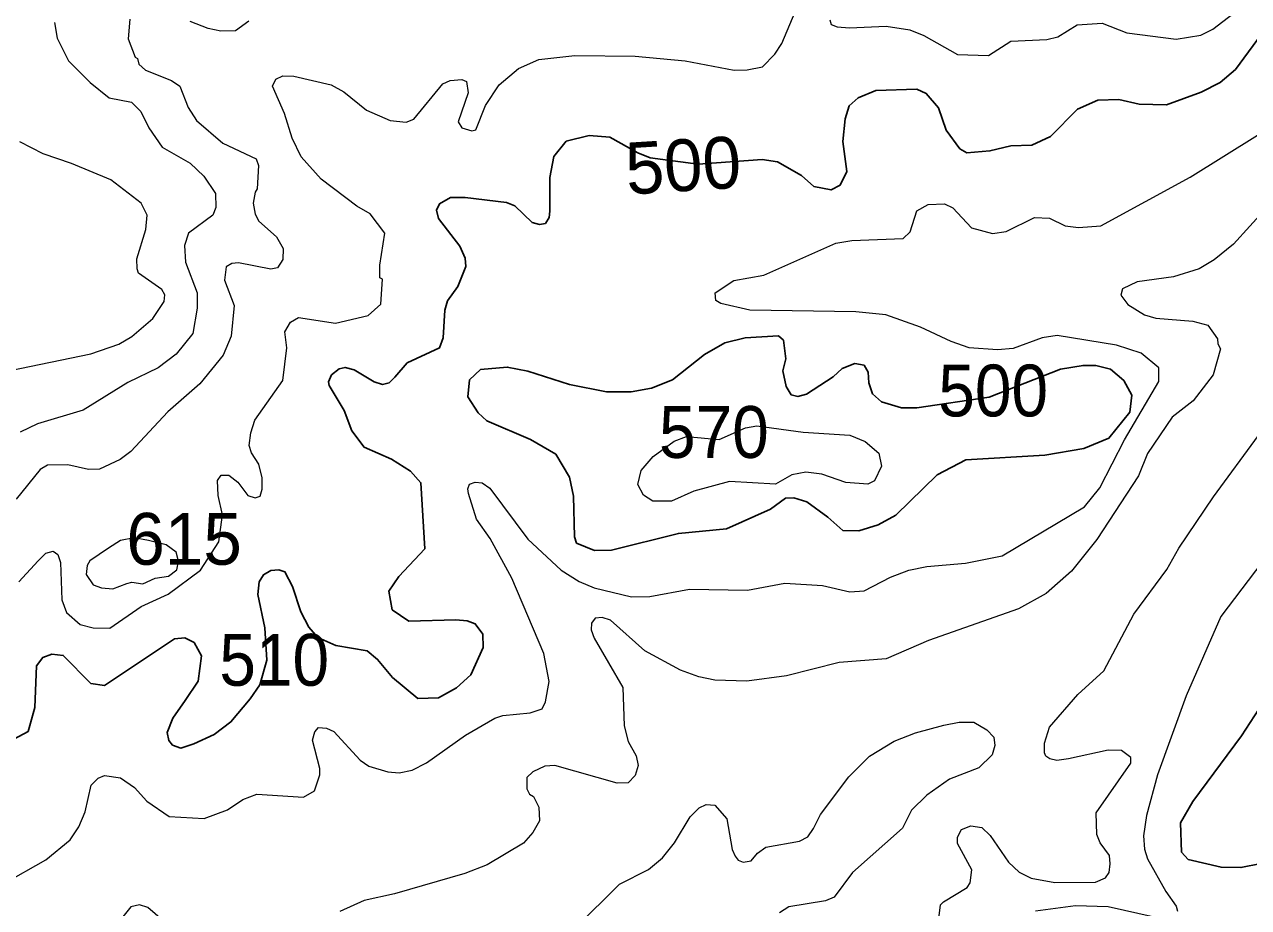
# Model space of a CAD drawing. Extents: x 499.9 to 555.3, y 9281.5 to 9336.8.
# Drawn here: x 542.724 to 546.505, y 9285.393 to 9288.118 of the extents above; entities that cross this region are included whole.
import ezdxf
from ezdxf.enums import TextEntityAlignment as Align

# ---------------------------------------------------------------- set-up
doc = ezdxf.new("R2010")
doc.units = 0
doc.header["$LTSCALE"] = 0.064
doc.layers.add('1', color=7, linetype='Continuous', lineweight=25)
doc.layers.add('2', color=7, linetype='Continuous', lineweight=13)
doc.layers.add('21', color=7, linetype='Continuous')
doc.layers.add('61', color=7, linetype='Continuous')

msp = doc.modelspace()

# ---------------------------------------------------------------- linework, layer by layer
at = {"layer": '1'}
for points in [[(545.354, 9287.915), (545.4801, 9287.9184), (545.5095, 9287.9048), (545.5474, 9287.8606), (545.5707, 9287.7925), (545.613, 9287.7349), (545.6348, 9287.7217), (545.7058, 9287.7279), (545.7703, 9287.7437), (545.835, 9287.7462), (545.8935, 9287.7726), (545.9765, 9287.8566), (546.0393, 9287.8849), (546.1037, 9287.8868), (546.1674, 9287.8727), (546.2509, 9287.8708), (546.3583, 9287.9093), (546.4172, 9287.9396), (546.4645, 9287.9794), (546.5447, 9288.0889)], [(545.2642, 9287.6646), (545.2517, 9287.7571), (545.2585, 9287.8276), (545.2715, 9287.8672), (545.2991, 9287.8917), (545.354, 9287.915)], [(543.2715, 9286.1697), (543.261, 9286.0915), (543.2204, 9286.0314), (543.1828, 9285.9773), (543.1652, 9285.9331), (543.1703, 9285.9078), (543.1816, 9285.8939), (543.2068, 9285.8841), (543.2475, 9285.8976), (543.3103, 9285.9267), (543.3617, 9285.9653), (543.4214, 9286.037), (543.4509, 9286.0799), (543.4728, 9286.1565), (543.4668, 9286.2561), (543.4447, 9286.3589), (543.4489, 9286.3975), (543.463, 9286.4196), (543.4847, 9286.4328), (543.5095, 9286.4346), (543.5285, 9286.4293), (543.5522, 9286.3837), (543.5783, 9286.3049), (543.602, 9286.2575), (543.6304, 9286.2258), (543.6858, 9286.2015), (543.7831, 9286.1854), (543.815, 9286.1584), (543.8613, 9286.1029), (543.9393, 9286.0379), (544.0028, 9286.0394), (544.0584, 9286.0711), (544.1029, 9286.111), (544.1412, 9286.1952), (544.1397, 9286.2363), (544.1163, 9286.2678), (544.092, 9286.278), (544.0561, 9286.2808), (543.9112, 9286.2764), (543.8599, 9286.3116), (543.8496, 9286.3687), (543.8804, 9286.4147), (543.9612, 9286.5), (543.9486, 9286.7037), (543.9168, 9286.7394), (543.8583, 9286.7764), (543.7732, 9286.8135), (543.7356, 9286.8637), (543.7118, 9286.9265), (543.6651, 9287.0044), (543.6628, 9287.0156), (543.6727, 9287.0368), (543.696, 9287.0559), (543.7147, 9287.0596), (543.7425, 9287.0525), (543.8048, 9287.0153), (543.83, 9287.0075), (543.851, 9287.0125), (543.868, 9287.0298), (543.9065, 9287.0739), (544.0056, 9287.1202), (544.0173, 9287.1515), (544.0225, 9287.2362), (544.0307, 9287.2654), (544.0631, 9287.3093), (544.0871, 9287.3713), (544.0852, 9287.3975), (544.0691, 9287.4341), (544.0025, 9287.5193), (543.9972, 9287.5452), (544.0058, 9287.5651), (544.0403, 9287.5844), (544.0849, 9287.5845), (544.2128, 9287.5685), (544.239, 9287.5585), (544.2927, 9287.5068), (544.3147, 9287.5005), (544.333, 9287.5036), (544.3445, 9287.5221), (544.3471, 9287.5418), (544.3467, 9287.6458), (544.3597, 9287.7109), (544.3977, 9287.7577), (544.4684, 9287.7754), (544.532, 9287.7703), (544.619, 9287.7222), (544.6566, 9287.7067), (544.8049, 9287.6868), (545.0024, 9287.7015), (545.0495, 9287.6944), (545.1237, 9287.652), (545.1623, 9287.6181), (545.2157, 9287.6076), (545.2432, 9287.6227), (545.2642, 9287.6646)], [(542.9296, 9286.0845), (542.9714, 9286.0778), (543.188, 9286.222), (543.2197, 9286.2251), (543.2481, 9286.2108), (543.2715, 9286.1697)], [(542.6178, 9285.873), (542.7356, 9285.936), (542.7565, 9286.0105), (542.7616, 9286.1385), (542.7808, 9286.1645), (542.8089, 9286.1745), (542.844, 9286.1707), (542.9296, 9286.0845)], [(546.5369, 9286.0051), (546.4835, 9285.9223), (546.3324, 9285.7202), (546.295, 9285.654), (546.2982, 9285.5635), (546.3187, 9285.5412), (546.4198, 9285.517), (546.4813, 9285.516), (546.5437, 9285.5285)]]:
    msp.add_lwpolyline(points, dxfattribs=at)
msp.add_lwpolyline([(546.0786, 9287.0542), (546.0335, 9287.0652), (545.9935, 9287.0659), (545.9243, 9287.0539), (545.7036, 9286.9677), (545.4803, 9286.9354), (545.4326, 9286.9354), (545.3708, 9286.954), (545.3433, 9286.9783), (545.3316, 9287.012), (545.3297, 9287.045), (545.3172, 9287.0663), (545.2886, 9287.072), (545.2497, 9287.0565), (545.2215, 9287.0302), (545.14, 9286.9772), (545.113, 9286.9705), (545.0917, 9286.9754), (545.0768, 9287.0008), (545.0663, 9287.049), (545.0753, 9287.0865), (545.0689, 9287.1436), (545.0531, 9287.1577), (544.9506, 9287.1514), (544.8878, 9287.1356), (544.8249, 9287.0995), (544.7261, 9287.0217), (544.6609, 9286.9956), (544.5981, 9286.9846), (544.5219, 9286.9845), (544.4079, 9287.0066), (544.2789, 9287.0484), (544.2153, 9287.0609), (544.1328, 9287.0538), (544.0991, 9287.0216), (544.0939, 9286.9687), (544.1254, 9286.9194), (544.1519, 9286.8944), (544.2869, 9286.8377), (544.3656, 9286.7918), (544.4074, 9286.7215), (544.4198, 9286.6623), (544.4231, 9286.5366), (544.4293, 9286.5174), (544.4843, 9286.4947), (544.5376, 9286.4961), (544.7442, 9286.5473), (544.8925, 9286.5613), (545.0285, 9286.6224), (545.0746, 9286.6558), (545.1008, 9286.657), (545.1406, 9286.6451), (545.2055, 9286.5971), (545.2516, 9286.5566), (545.3015, 9286.555), (545.3612, 9286.5737), (545.4151, 9286.6032), (545.5433, 9286.7277), (545.6319, 9286.774), (545.8753, 9286.789), (545.9962, 9286.8098), (546.0735, 9286.8412), (546.138, 9286.9214), (546.1443, 9286.9746), (546.1194, 9287.0197)], close=True, dxfattribs=at)
at = {"layer": '2'}
for points in [[(543.7107, 9287.9104), (543.7801, 9287.8537), (543.854, 9287.8217), (543.9028, 9287.8169), (543.9268, 9287.8258), (544.0162, 9287.935), (544.0386, 9287.9459), (544.0749, 9287.9484), (544.0892, 9287.9428), (544.0951, 9287.9076), (544.0639, 9287.818), (544.0753, 9287.7994), (544.1059, 9287.7902), (544.1188, 9287.7934), (544.1485, 9287.8679), (544.1902, 9287.9325), (544.2505, 9287.9821), (544.3133, 9288.0099), (544.4245, 9288.0222), (544.6108, 9288.0207), (544.7653, 9288.0061), (544.9165, 9287.9778), (544.9563, 9287.978), (545.0037, 9287.9881), (545.0418, 9288.0264), (545.0631, 9288.0595), (545.113, 9288.1766)], [(545.2112, 9288.1322), (545.2156, 9288.1179), (545.2341, 9288.111), (545.2722, 9288.1083), (545.3861, 9288.1129), (545.459, 9288.1022), (545.5017, 9288.0844), (545.6064, 9288.0258), (545.7016, 9288.0227), (545.7702, 9288.0668), (545.8823, 9288.0716), (545.9162, 9288.0803), (545.9757, 9288.1173), (546.0527, 9288.1223), (546.1284, 9288.0926), (546.2812, 9288.0733), (546.3576, 9288.0858), (546.3949, 9288.1035), (546.4735, 9288.1644)], [(543.0496, 9288.1345), (543.0448, 9288.0738), (543.0663, 9288.0177), (543.0733, 9288.0134), (543.0772, 9287.9963), (543.098, 9287.9775), (543.1784, 9287.9457), (543.2036, 9287.9282), (543.2298, 9287.8625), (543.256, 9287.8224), (543.3369, 9287.7523), (543.4395, 9287.7032), (543.4471, 9287.6826), (543.4425, 9287.611), (543.4363, 9287.6005), (543.4308, 9287.5668), (543.4364, 9287.5327), (543.4485, 9287.5109), (543.5026, 9287.4625), (543.5237, 9287.4271), (543.5218, 9287.3925), (543.5053, 9287.3668), (543.4849, 9287.3629), (543.3852, 9287.3824), (543.3647, 9287.3806), (543.3475, 9287.3698), (543.3421, 9287.3291), (543.3723, 9287.2509), (543.363, 9287.1564), (543.3382, 9287.0973), (543.2654, 9287.0095), (543.1673, 9286.9225), (543.0532, 9286.8005), (543.0202, 9286.7757), (542.9563, 9286.7461), (542.9221, 9286.7445), (542.8585, 9286.7586), (542.7951, 9286.7577), (542.7731, 9286.7447), (542.6988, 9286.653)], [(542.8166, 9288.1248), (542.8254, 9288.0757), (542.8607, 9288.0058), (542.9276, 9287.939), (542.9857, 9287.8916), (543.0547, 9287.8784), (543.0832, 9287.8497), (543.1084, 9287.7994), (543.1494, 9287.7395), (543.2363, 9287.6906), (543.2786, 9287.6498), (543.3146, 9287.5964), (543.3151, 9287.5537), (543.3057, 9287.5296), (543.2304, 9287.4741), (543.2183, 9287.4366), (543.2217, 9287.3849), (543.2578, 9287.2901), (543.2579, 9287.2424), (543.2443, 9287.1648), (543.1926, 9287.1008), (543.1369, 9287.059), (543.044, 9287.0128), (542.9053, 9286.9277), (542.7649, 9286.8855), (542.7106, 9286.8604)], [(543.4171, 9288.1281), (543.3756, 9288.0989), (543.3312, 9288.0976), (543.2913, 9288.1056), (543.2363, 9288.1271)], [(543.4908, 9287.9279), (543.501, 9287.9491), (543.5222, 9287.96), (543.5558, 9287.9587), (543.6711, 9287.9317), (543.7107, 9287.9104)], [(542.7069, 9286.3983), (542.7664, 9286.4628), (542.7907, 9286.4864), (542.8124, 9286.4923), (542.827, 9286.4824), (542.8357, 9286.4577), (542.8394, 9286.3424), (542.8543, 9286.3029), (542.8959, 9286.2666), (542.9365, 9286.2557), (542.988, 9286.2545), (543.0847, 9286.3216), (543.1679, 9286.3595), (543.2679, 9286.434), (543.3249, 9286.5211), (543.3355, 9286.6052), (543.3224, 9286.6645), (543.3208, 9286.7111), (543.3319, 9286.7272), (543.3551, 9286.7273), (543.3828, 9286.7052), (543.4139, 9286.6648), (543.4364, 9286.6567), (543.4526, 9286.6627), (543.4587, 9286.684), (543.4587, 9286.7192), (543.448, 9286.7613), (543.4255, 9286.7965), (543.4186, 9286.819), (543.4233, 9286.8583), (543.4356, 9286.8974), (543.5222, 9287.0195), (543.5341, 9287.1198), (543.5285, 9287.1695), (543.5459, 9287.1997), (543.5705, 9287.2138), (543.6853, 9287.1962), (543.786, 9287.2198), (543.8246, 9287.2546), (543.8303, 9287.3321), (543.8214, 9287.3366), (543.8214, 9287.3754), (543.8371, 9287.4746), (543.7924, 9287.5336), (543.7507, 9287.558), (543.641, 9287.6404), (543.5789, 9287.7101), (543.5509, 9287.7676), (543.5269, 9287.844), (543.4908, 9287.9279)], [(543.7875, 9285.8294), (543.8467, 9285.8113), (543.8819, 9285.8085), (543.9219, 9285.8161), (543.9661, 9285.8397), (544.0866, 9285.9248), (544.1769, 9285.9773), (544.2018, 9285.9852), (544.2861, 9285.9931), (544.3236, 9286.0056), (544.3339, 9286.0273), (544.3449, 9286.0901), (544.3287, 9286.1767), (544.2298, 9286.4097), (544.1623, 9286.5319), (544.1207, 9286.5915), (544.0955, 9286.6702), (544.0934, 9286.6855), (544.0986, 9286.6995), (544.1159, 9286.7058), (544.1382, 9286.703), (544.1613, 9286.6873), (544.2793, 9286.5299), (544.3817, 9286.4339), (544.4374, 9286.3989), (544.4837, 9286.3789), (544.5989, 9286.3512), (544.6554, 9286.3528), (544.7779, 9286.375), (544.957, 9286.3718), (545.0724, 9286.3941), (545.1894, 9286.3862), (545.2734, 9286.3673), (545.3174, 9286.3704), (545.3991, 9286.4127), (545.4551, 9286.4341), (545.5116, 9286.445), (545.6305, 9286.4553), (545.744, 9286.4785), (545.9986, 9286.6297), (546.0452, 9286.6876), (546.1218, 9286.8358), (546.2277, 9287.0168), (546.2272, 9287.0581), (546.1731, 9287.1042), (546.0966, 9287.128), (545.9135, 9287.1579), (545.8674, 9287.1514), (545.7782, 9287.1182), (545.7294, 9287.1136), (545.6419, 9287.1206), (545.5862, 9287.1397), (545.4921, 9287.1843), (545.3843, 9287.2217), (545.2918, 9287.2314), (544.9644, 9287.2368), (544.8745, 9287.2571), (544.8594, 9287.2665), (544.8574, 9287.2898), (544.9156, 9287.3284), (545.0073, 9287.3449), (545.23, 9287.4428), (545.2796, 9287.4512), (545.4383, 9287.4576), (545.4592, 9287.4788), (545.4801, 9287.5429), (545.5156, 9287.5623), (545.5656, 9287.5648), (545.5917, 9287.5521), (545.6494, 9287.4905), (545.7138, 9287.4733), (545.756, 9287.4794), (545.8435, 9287.5224), (545.8904, 9287.5207), (545.9383, 9287.4972), (545.9799, 9287.4915), (546.0482, 9287.4968), (546.324, 9287.647), (546.6364, 9287.8413)], [(542.6803, 9287.0498), (542.9294, 9287.1022), (543.0159, 9287.1313), (543.0558, 9287.1549), (543.121, 9287.2106), (543.1555, 9287.2634), (543.1575, 9287.2838), (543.149, 9287.3002), (543.076, 9287.3507), (543.0721, 9287.3642), (543.0714, 9287.3945), (543.0993, 9287.4858), (543.1032, 9287.5302), (543.0844, 9287.5669), (542.9907, 9287.6387), (542.8696, 9287.6896), (542.7816, 9287.7189), (542.7095, 9287.7561)], [(546.5593, 9287.5515), (546.4586, 9287.4398), (546.3985, 9287.3916), (546.3525, 9287.3637), (546.273, 9287.3397), (546.1604, 9287.3242), (546.1155, 9287.3025), (546.1105, 9287.2826), (546.1317, 9287.2543), (546.1834, 9287.2218), (546.218, 9287.2118), (546.3329, 9287.2026), (546.379, 9287.1902), (546.4091, 9287.1477), (546.4095, 9287.1327), (546.4186, 9287.1174), (546.3955, 9287.037), (546.3339, 9286.957), (546.269, 9286.9057), (546.1929, 9286.7936), (546.1647, 9286.7255), (546.0366, 9286.5288), (545.9577, 9286.4313), (545.8796, 9286.3615), (545.7948, 9286.3148), (545.5166, 9286.2169), (545.3858, 9286.1606), (545.2403, 9286.1488), (545.078, 9286.1075), (544.9554, 9286.0918), (544.8561, 9286.0948), (544.8074, 9286.1047), (544.7502, 9286.1254), (544.6401, 9286.1852), (544.5341, 9286.2801), (544.508, 9286.2879), (544.487, 9286.2853), (544.4756, 9286.2701), (544.4741, 9286.2496), (544.484, 9286.2242), (544.5727, 9286.0717), (544.5763, 9285.9536), (544.5887, 9285.9046), (544.6138, 9285.8609), (544.62, 9285.8308), (544.6102, 9285.7999), (544.5884, 9285.777), (544.5543, 9285.7766), (544.3625, 9285.8306), (544.3315, 9285.8291), (544.2941, 9285.8115)], [(545.8329, 9285.4829), (545.9063, 9285.4695), (546.0318, 9285.471), (546.0628, 9285.4847), (546.0744, 9285.501), (546.0774, 9285.5272), (546.0749, 9285.5531), (546.0462, 9285.5927), (546.0362, 9285.6181), (546.0338, 9285.6851), (546.1412, 9285.8379), (546.1414, 9285.856), (546.1124, 9285.8768), (546.0711, 9285.8783), (545.9485, 9285.8516), (545.9127, 9285.8469), (545.8911, 9285.8516), (545.8792, 9285.8595), (545.8749, 9285.8706), (545.8744, 9285.8996), (545.8904, 9285.9491), (545.9776, 9286.0498), (546.0575, 9286.1236), (546.1508, 9286.2984), (546.2528, 9286.4364), (546.2896, 9286.5017), (546.397, 9286.6606), (546.5356, 9286.8494)], [(546.568, 9286.4874), (546.419, 9286.2906), (546.3124, 9286.0462), (546.2241, 9285.802), (546.1898, 9285.6771), (546.1802, 9285.6143), (546.1835, 9285.5723), (546.1926, 9285.5432), (546.2489, 9285.4423), (546.2815, 9285.397), (546.2858, 9285.3811)], [(543.6213, 9285.9344), (543.6327, 9285.9483), (543.6567, 9285.9458), (543.6795, 9285.9356), (543.7606, 9285.8474), (543.7875, 9285.8294)], [(544.4261, 9285.3294), (544.5615, 9285.4645), (544.6512, 9285.5098), (544.6951, 9285.5459), (544.7317, 9285.592), (544.7804, 9285.6725), (544.8082, 9285.7), (544.8297, 9285.711), (544.8564, 9285.709), (544.8932, 9285.6662), (544.9102, 9285.5713), (544.9193, 9285.5515), (544.9289, 9285.5387), (544.9444, 9285.5329), (544.9687, 9285.5367), (544.9886, 9285.5601), (545.0142, 9285.5784), (545.1179, 9285.5972), (545.1433, 9285.6105), (545.1612, 9285.6367), (545.1831, 9285.6801), (545.2701, 9285.7962), (545.3346, 9285.8601), (545.4099, 9285.9056), (545.476, 9285.9322), (545.5641, 9285.9551), (545.6107, 9285.965), (545.6563, 9285.9645), (545.697, 9285.941), (545.7182, 9285.9181), (545.7209, 9285.893), (545.7134, 9285.8638), (545.6717, 9285.8241), (545.5811, 9285.7889), (545.5113, 9285.7398), (545.4639, 9285.6926), (545.436, 9285.6373), (545.2818, 9285.5006), (545.2249, 9285.4249), (545.1987, 9285.4132), (545.0851, 9285.395), (545.056, 9285.3766)], [(542.6591, 9285.4657), (542.79, 9285.5395), (542.8658, 9285.6011), (542.8919, 9285.6414), (542.9122, 9285.6883), (542.9304, 9285.7699), (542.9517, 9285.7916), (542.9717, 9285.8), (543.0208, 9285.7929), (543.0643, 9285.7632), (543.1021, 9285.7212), (543.1707, 9285.6737), (543.2794, 9285.667), (543.3518, 9285.694), (543.3988, 9285.7259), (543.4419, 9285.7427), (543.5857, 9285.7337), (543.6202, 9285.7526), (543.6362, 9285.8018), (543.6368, 9285.8218), (543.6138, 9285.9091), (543.6213, 9285.9344)], [(544.2941, 9285.8115), (544.276, 9285.7937), (544.2762, 9285.7586), (544.2836, 9285.7428), (544.2964, 9285.735), (544.3127, 9285.7025)], [(544.3127, 9285.7025), (544.3147, 9285.6602), (544.2944, 9285.6238), (544.2659, 9285.5909), (544.1531, 9285.5247), (544.084, 9285.498), (543.8675, 9285.4349), (543.7733, 9285.4146), (543.6978, 9285.3806)], [(545.5397, 9285.2907), (545.5534, 9285.4007), (545.5626, 9285.4104), (545.6358, 9285.4544), (545.645, 9285.4685), (545.65, 9285.5094), (545.6058, 9285.5905), (545.6057, 9285.6102), (545.6186, 9285.6331), (545.6468, 9285.6444)], [(545.6468, 9285.6444), (545.6809, 9285.6391), (545.7063, 9285.6152), (545.7637, 9285.5325), (545.7966, 9285.5014), (545.8329, 9285.4829)], [(543.2028, 9285.3082), (543.1051, 9285.3928), (543.0791, 9285.4009), (543.0527, 9285.3945), (543.0285, 9285.3634)], [(546.2136, 9285.3625), (546.0711, 9285.3947), (545.9708, 9285.3978), (545.8473, 9285.3815)]]:
    msp.add_lwpolyline(points, dxfattribs=at)
for points in [[(545.1873, 9286.7307), (545.1377, 9286.7364), (545.0939, 9286.7283), (545.0435, 9286.699), (544.9014, 9286.7077), (544.7919, 9286.6781), (544.7228, 9286.6465), (544.6648, 9286.6474), (544.6359, 9286.6652), (544.6185, 9286.6983), (544.6285, 9286.7411), (544.6663, 9286.7846), (544.7311, 9286.832), (544.7693, 9286.8461), (544.8693, 9286.8369), (544.9514, 9286.873), (544.9864, 9286.8794), (545.1296, 9286.8604), (545.2736, 9286.8507), (545.3212, 9286.8312), (545.3627, 9286.795), (545.3711, 9286.7547), (545.3495, 9286.7097), (545.3286, 9286.6998), (545.2609, 9286.7044)], [(542.9622, 9286.3791), (542.9971, 9286.3759), (543.04, 9286.3928), (543.0558, 9286.3964), (543.09, 9286.3916), (543.1281, 9286.4092), (543.1694, 9286.4154), (543.1947, 9286.4345), (543.2002, 9286.4614), (543.1929, 9286.4891), (543.1619, 9286.5125), (543.1076, 9286.5256), (543.0626, 9286.5334), (543.0206, 9286.5256), (542.9834, 9286.5021), (542.9265, 9286.4623), (542.9176, 9286.4481), (542.9144, 9286.4208), (542.9361, 9286.389)]]:
    msp.add_lwpolyline(points, close=True, dxfattribs=at)

# ---------------------------------------------------------------- texts
at = {"layer": '21', "width": 0.95}
for s, p in [('570', (544.6839, 9286.7804)), ('510', (543.326, 9286.0772))]:
    msp.add_text(s, height=0.16, dxfattribs=at).set_placement(p)
at = {"layer": '21'}
msp.add_text('615', height=0.16, dxfattribs=at).set_placement((543.0387, 9286.4507))
at = {"layer": '61'}
msp.add_text('500', height=0.16, rotation=3.54, dxfattribs=at).set_placement((544.7636, 9287.6041), align=Align.CENTER)
at = {"layer": '61', "width": 0.95}
msp.add_text('500', height=0.16, dxfattribs=at).set_placement((545.7161, 9286.9085), align=Align.CENTER)

doc.saveas('drawing.dxf')
